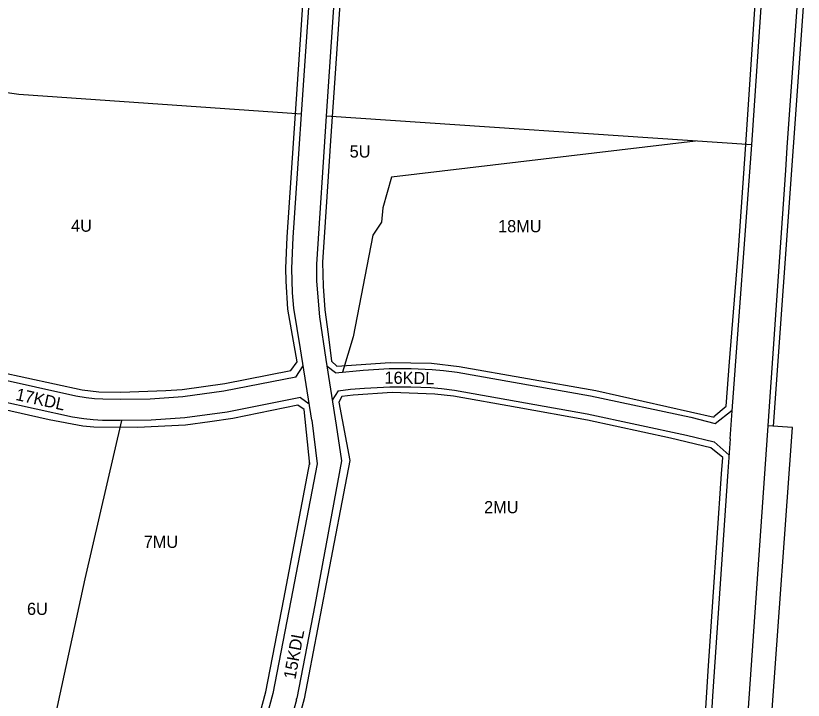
# Model space of a CAD drawing. Extents: x 7428203 to 7432868, y 5542672 to 5545406.
# Drawn here: x 7431420 to 7432066, y 5543396 to 5543958 of the extents above; entities that cross this region are included whole.
import ezdxf

# ---------------------------------------------------------------- set-up
doc = ezdxf.new("R2010")
doc.units = 0
for name, color, linetype in [('_GRANICA_MIASTA', 7, 'Continuous'), ('granicaBulwary', 7, 'Continuous'), ('MPZP_uchwalone_nieobowiazujace jeszcze_SZRAF', 7, 'Continuous')]:
    doc.layers.add(name, color=color, linetype=linetype)

msp = doc.modelspace()

# ---------------------------------------------------------------- linework, layer by layer
at = {"layer": '_GRANICA_MIASTA'}
for p, q in [((7432024.19, 5543851.74), (7432053.71, 5544292.64)), ((7431696.5, 5544197.97), (7431674.68, 5543875.42)), ((7432061.05, 5543964.92), (7432053.02, 5543849.76)), ((7431422.33, 5543893.08), (7431386.19, 5543898.41)), ((7431654.46, 5543877.07), (7431422.33, 5543893.08)), ((7431652.52, 5543848.58), (7431654.46, 5543877.07)), ((7431674.68, 5543875.42), (7431666.71, 5543753.84)), ((7432024.19, 5543851.74), (7431674.68, 5543875.42)), ((7431647.57, 5543775.78), (7431652.52, 5543848.58)), ((7432008, 5543633.54), (7432024.19, 5543851.74)), ((7432053.02, 5543849.76), (7432051.74, 5543831.18)), ((7432051.74, 5543831.18), (7432037.23, 5543621.26)), ((7431646.45, 5543750.43), (7431647.57, 5543775.78)), ((7431666.71, 5543753.84), (7431666.78, 5543739.82)), ((7431646.98, 5543730.32), (7431646.45, 5543750.43)), ((7431666.78, 5543739.82), (7431669.08, 5543710.77)), ((7431648.08, 5543717.76), (7431646.98, 5543730.32)), ((7431653.42, 5543684.5), (7431648.08, 5543717.76)), ((7431669.08, 5543710.77), (7431674.42, 5543675.7)), ((7431662.92, 5543625.91), (7431653.42, 5543684.5)), ((7431674.42, 5543675.7), (7431682.81, 5543621.83)), ((7431649.61, 5543661.01), (7431655.72, 5543670.33)), ((7431682.23, 5543664.8), (7431675.31, 5543669.98)), ((7431684.49, 5543649.98), (7431679.61, 5543642.38)), ((7431653.54, 5543644.48), (7431660.75, 5543639.3)), ((7432006.42, 5543610.6), (7432008, 5543633.54)), ((7431662.92, 5543625.91), (7431667.23, 5543590.08)), ((7431682.81, 5543621.83), (7431687.09, 5543592.47)), ((7432037.23, 5543621.26), (7432020.68, 5543381.69)), ((7432033.73, 5543287.48), (7432057.57, 5543619.82)), ((7432057.57, 5543619.82), (7432037.23, 5543621.26)), ((7432006.42, 5543610.6), (7432004.56, 5543583.62)), ((7431687.09, 5543592.47), (7431665.34, 5543474.03)), ((7432004.56, 5543583.62), (7431991.84, 5543399.38)), ((7431665.33, 5543473.98), (7431650.48, 5543397.55)), ((7431650.15, 5543396.15), (7431628.87, 5543317.63)), ((7431991.84, 5543399.38), (7431988.98, 5543346.68))]:
    msp.add_line(p, q, dxfattribs=at)
for points in [[(7431654.46, 5543877.07), (7431672.85, 5544147.41), (7431697.38, 5544505.35), (7431680.1, 5544526.46), (7431451.66, 5544545.79), (7431389.69, 5544552.15)], [(7431978.02, 5543854.87), (7431728.36, 5543825.28), (7431721.14, 5543800.07), (7431720.06, 5543788.32), (7431713.06, 5543777.73), (7431696.67, 5543694.29), (7431688.14, 5543665.36)], [(7431649.61, 5543661.01), (7431590.67, 5543649.59), (7431556.92, 5543645.08), (7431530.11, 5543643.19), (7431505.43, 5543642.9), (7431491.22, 5543643.07), (7431484.24, 5543643.38), (7431477.62, 5543644.1), (7431468.99, 5543645.49), (7431402.48, 5543660.21), (7431391.69, 5543673.42)], [(7431682.23, 5543664.8), (7431704.97, 5543666.95), (7431726.48, 5543668.28), (7431744.45, 5543668.21), (7431761.56, 5543667.53), (7431770.9, 5543666.64), (7431782.26, 5543665.32), (7431891.78, 5543645.91), (7431974.06, 5543628.18), (7431993.99, 5543623.12), (7432008.05, 5543634.19)], [(7431684.49, 5543649.98), (7431694.63, 5543651.26), (7431706.13, 5543652), (7431726.91, 5543653.28), (7431744.12, 5543653.21), (7431760.55, 5543652.56), (7431769.33, 5543651.72), (7431780.08, 5543650.48), (7431888.89, 5543631.18), (7431970.63, 5543613.57), (7431993.13, 5543608.19), (7432005.49, 5543597.11)], [(7431653.54, 5543644.48), (7431593.24, 5543632.39), (7431558.54, 5543627.75), (7431530.83, 5543625.8), (7431505.53, 5543625.5), (7431490.89, 5543625.68), (7431483.19, 5543626.02), (7431475.72, 5543626.83), (7431466.29, 5543628.35), (7431406.24, 5543641.45), (7431388.58, 5543632.9)], [(7431436.3, 5543305.53), (7431440.68, 5543328.86), (7431476.66, 5543495.49), (7431506.81, 5543625.52)], [(7431667.23, 5543590.08), (7431645.7, 5543477.8), (7431630.84, 5543401.36), (7431606.51, 5543311.31), (7431598.84, 5543303.62)]]:
    msp.add_lwpolyline(points, dxfattribs=at)
for centre, radius, start, end in [((7431665.38, 5543474), 0.057, 142.12502, 195.25512), ((7431635.42, 5543400.36), 15.32, 344.04512, 349.42822)]:
    msp.add_arc(centre, radius, start, end, dxfattribs=at)
at = {"layer": 'MPZP_uchwalone_nieobowiazujace jeszcze_SZRAF'}
for p, q in [((7432066.4, 5543964.87), (7432041.61, 5543620.95)), ((7431642.58, 5543776), (7431649.44, 5543877.57)), ((7431641.45, 5543750.66), (7431642.58, 5543776)), ((7431641.8, 5543739.94), (7431641.45, 5543750.66)), ((7431643.15, 5543716.96), (7431641.8, 5543739.94)), ((7431650.7, 5543673.62), (7431643.15, 5543716.96)), ((7431728.86, 5543648.44), (7431696.88, 5543646.42)), ((7431763.94, 5543647.21), (7431728.86, 5543648.44)), ((7431687.59, 5543645.34), (7431684.91, 5543640.62)), ((7431696.88, 5543646.42), (7431687.59, 5543645.34)), ((7431779.14, 5543645.57), (7431763.94, 5543647.21)), ((7431831.52, 5543636.28), (7431779.14, 5543645.57)), ((7431447.06, 5543626.25), (7431407.18, 5543635.16)), ((7431651.38, 5543638.12), (7431598.08, 5543627.19)), ((7431656.52, 5543634.64), (7431651.38, 5543638.12)), ((7431661.27, 5543589.36), (7431656.52, 5543634.64)), ((7431684.91, 5543640.62), (7431694.1, 5543592.69)), ((7431889.27, 5543625.74), (7431831.52, 5543636.28)), ((7431474.92, 5543620.89), (7431447.06, 5543626.25)), ((7431559.15, 5543621.78), (7431519.67, 5543619.7)), ((7431579.12, 5543624.58), (7431559.15, 5543621.78)), ((7431598.08, 5543627.19), (7431579.12, 5543624.58)), ((7431957.42, 5543611.08), (7431889.27, 5543625.74)), ((7431483.83, 5543619.99), (7431474.92, 5543620.89)), ((7431519.67, 5543619.7), (7431483.83, 5543619.99)), ((7431990.45, 5543603.1), (7431957.42, 5543611.08)), ((7432000.4, 5543595.17), (7431990.45, 5543603.1)), ((7431999.37, 5543581.86), (7432000.4, 5543595.17)), ((7431988.54, 5543424.24), (7431999.37, 5543581.86)), ((7431984.1, 5543349.02), (7431988.54, 5543424.24))]:
    msp.add_line(p, q, dxfattribs=at)
for points in [[(7431649.47, 5543877.41), (7431655.88, 5543974.89), (7431665.17, 5544116.21), (7431681.81, 5544351.27), (7431692.14, 5544503.86), (7431677.57, 5544521.65), (7431530.62, 5544534.23), (7431408.5, 5544545.23)], [(7432045.54, 5544492.68), (7431860.4, 5544508.47), (7431740.58, 5544516.97), (7431722.06, 5544501.46), (7431708.61, 5544303.22), (7431682.26, 5543914.58), (7431678.23, 5543855.15), (7431673.15, 5543780.29), (7431671.48, 5543755.53), (7431672.12, 5543735.74), (7431673.66, 5543716.32), (7431676.18, 5543696.55), (7431679.04, 5543674.23), (7431683.33, 5543670.2), (7431727.11, 5543673.28), (7431761.22, 5543672.6), (7431783.87, 5543669.93), (7431896.16, 5543650.19), (7431993.34, 5543628.23)], [(7431992.94, 5543628.74), (7431992.94, 5543628.74), (7432003.08, 5543637.39), (7432005.96, 5543673.78), (7432013.24, 5543765.46), (7432019.21, 5543852.08), (7432042.45, 5544201.74), (7432061.21, 5544477.78), (7432045.87, 5544492.57)], [(7431401.46, 5543671.4), (7431405.81, 5543665.62), (7431474.26, 5543650.72), (7431488.04, 5543649.22), (7431505.94, 5543648.91), (7431543.09, 5543650.12), (7431556.31, 5543651.05), (7431591.53, 5543655.87), (7431645.69, 5543666.48), (7431650.7, 5543673.62)], [(7431594.59, 5543307.86), (7431601.14, 5543314.41), (7431625, 5543402.72), (7431639.8, 5543478.94), (7431661.34, 5543591.21)], [(7431694.1, 5543592.69), (7431674.64, 5543491.6), (7431660.37, 5543416.96), (7431656.51, 5543397.07), (7431635.8, 5543320.41)]]:
    msp.add_lwpolyline(points, dxfattribs=at)

# ---------------------------------------------------------------- texts
at = {"layer": 'granicaBulwary'}
for s, p in [('5U', (7431693.92, 5543841.42)), ('4U', (7431465.17, 5543780.51)), ('18MU', (7431815.81, 5543780.07)), ('2MU', (7431804.33, 5543549.45)), ('7MU', (7431524.82, 5543520.96)), ('6U', (7431428.94, 5543465.97))]:
    msp.add_text(s, height=10, dxfattribs=at).set_placement(p)
for s, rotation, p in [('16KDL', 359.24142, (7431722.48, 5543655.82)), ('17KDL', 347.50629, (7431419.06, 5543642.52)), ('15KDL', 79.5894, (7431649.34, 5543412.65))]:
    msp.add_text(s, height=10, rotation=rotation, dxfattribs=at).set_placement(p)

doc.saveas('drawing.dxf')
